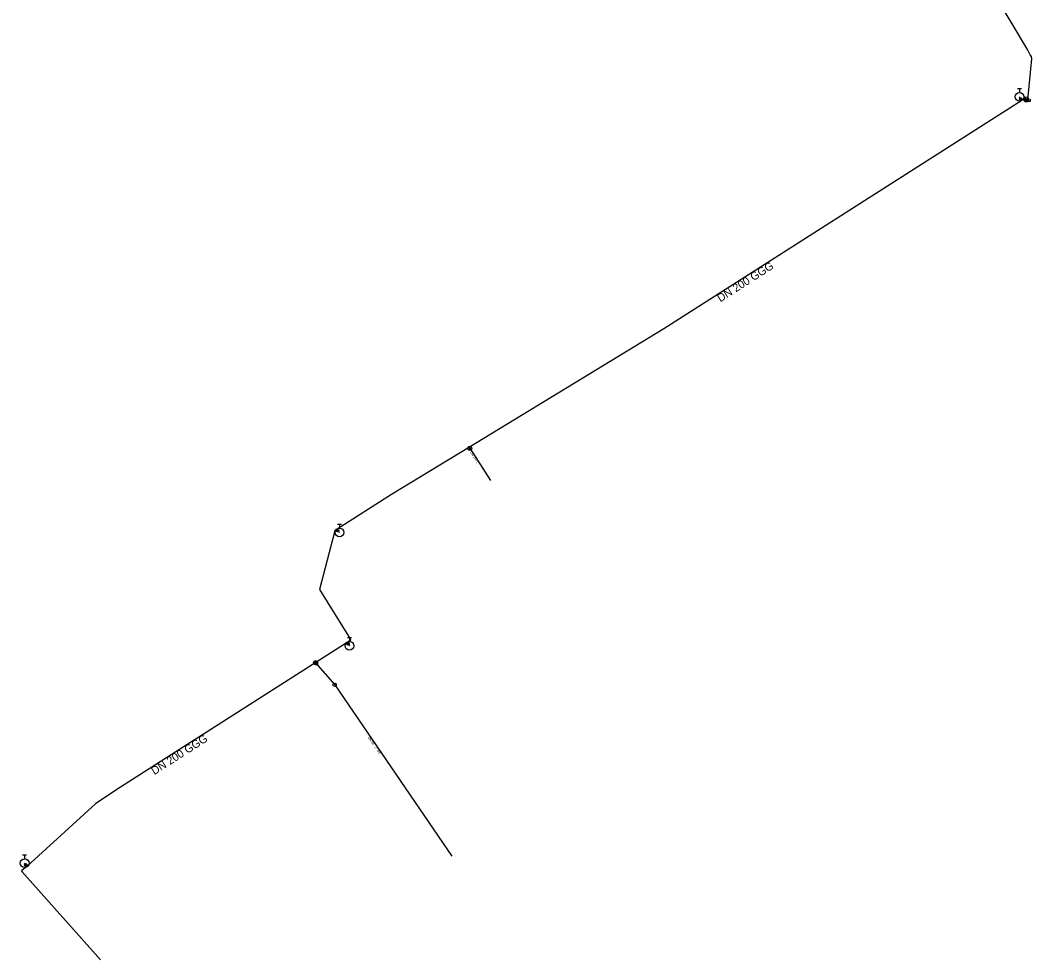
# Model space of a CAD drawing. Extents: x -451555 to -451079, y -1102113 to -1101586.
# Drawn here: x -451282.2 to -451079.4, y -1102113.4 to -1101925 of the extents above; entities that cross this region are included whole.
import ezdxf

# ---------------------------------------------------------------- set-up
doc = ezdxf.new("R2010")
doc.units = 0
for name, color, linetype in [('_hydrantova_odbocka_', 7, 'Continuous'), ('_pripojka_prevzato_z_dokumentace_', 7, 'Continuous'), ('_pripojka_priblizne_', 7, 'Continuous'), ('_voda_smvak_prevzato_z_dokumentace_', 7, 'Continuous'), ('Default', 7, 'Continuous'), ('MoLevel 27', 7, 'Continuous'), ('MoLevel 28', 7, 'Continuous'), ('MoLevel 30', 7, 'Continuous'), ('MoLevel 32', 7, 'Continuous'), ('MoLevel 42', 7, 'Continuous'), ('MoLevel 43', 7, 'Continuous'), ('MoLevel 46', 7, 'Continuous'), ('MoLevel 53', 7, 'Continuous')]:
    doc.layers.add(name, color=color, linetype=linetype)

# ---------------------------------------------------------------- blocks, each defined once
blk = doc.blocks.new('_uzaver_')
at = {"layer": 'Default'}
for p, q in [((-0.000035, -0.000035), (0.000035, 0.000035)), ((0.000035, -0.000035), (-0.000035, 0.000035))]:
    blk.add_line(p, q, dxfattribs=at)
for radius in [0.00005, 0.0000025]:
    blk.add_circle((0, 0), radius, dxfattribs=at)
blk = doc.blocks.new('_uzaver_pripojka_')
at = {"layer": 'Default'}
for p, q in [((-0.000035, -0.000035), (0.000035, 0.000035)), ((0.000035, -0.000035), (-0.000035, 0.000035))]:
    blk.add_line(p, q, dxfattribs=at)
for radius in [0.00005, 0.0000025]:
    blk.add_circle((0, 0), radius, dxfattribs=at)
blk = doc.blocks.new('_hydrant_voda_')
at = {"layer": 'Default'}
for p, q in [((-0.000023, 0.000095), (0.000023, 0.000095)), ((0, 0.000095), (0, 0.00005))]:
    blk.add_line(p, q, dxfattribs=at)
blk.add_circle((0, 0), 0.00005, dxfattribs=at)
blk = doc.blocks.new('_zaslepeni_')
at = {"layer": 'Default'}
blk.add_lwpolyline([(-0.00004, -0.00005), (0, -0.00005), (0, 0.00005), (-0.00004, 0.00005), (-0.00004, 0.00005)], dxfattribs=at)
blk = doc.blocks.new('_sachta_voda_')
at = {"layer": 'Default'}
blk.add_circle((0, 0), 0.000035, dxfattribs=at)
blk = doc.blocks.new('_poklop_voda_')
at = {"layer": 'Default'}
blk.add_circle((0, 0), 0.00002, dxfattribs=at)

msp = doc.modelspace()

# ---------------------------------------------------------------- linework, layer by layer
at = {"layer": '_hydrantova_odbocka_'}
for p, q in [((-451081.59, -1101940.76), (-451081.82, -1101940.32)), ((-451081.37, -1101941.05), (-451081.59, -1101940.76)), ((-451218.64, -1102027.02), (-451218.56, -1102027.33)), ((-451218.56, -1102027.33), (-451218.18, -1102027.69)), ((-451216.63, -1102049.77), (-451216.46, -1102050.04)), ((-451216.46, -1102050.04), (-451216.18, -1102050.42)), ((-451281.05, -1102094.37), (-451281.3, -1102094.02)), ((-451280.77, -1102094.65), (-451281.05, -1102094.37))]:
    msp.add_line(p, q, dxfattribs=at)
at = {"layer": '_pripojka_prevzato_z_dokumentace_'}
msp.add_line((-451222.97, -1102053.82), (-451219.13, -1102058.26), dxfattribs=at)
at = {"layer": '_pripojka_priblizne_'}
msp.add_line((-451219.13, -1102058.26), (-451195.67, -1102092.62), dxfattribs=at)
msp.add_lwpolyline([(-451192.13, -1102010.59), (-451192.05, -1102010.82), (-451187.91, -1102017.27)], dxfattribs=at)
at = {"layer": '_voda_smvak_prevzato_z_dokumentace_'}
for p, q in [((-451080.15, -1101940.92), (-451080.5, -1101940.86)), ((-451080.14, -1101941.19), (-451080.15, -1101940.92))]:
    msp.add_line(p, q, dxfattribs=at)
for points in [[(-451079.67, -1101931.88), (-451080.22, -1101930.82), (-451126.34, -1101853.56), (-451153.78, -1101812.57), (-451163.8, -1101796.36), (-451163.8, -1101796.36)], [(-451080.15, -1101940.92), (-451079.37, -1101932.69), (-451079.41, -1101932.26), (-451079.67, -1101931.88)], [(-451080.5, -1101940.86), (-451080.98, -1101940.79), (-451081.37, -1101941.05), (-451153.11, -1101986.86), (-451192.13, -1102010.59)], [(-451192.13, -1102010.59), (-451207.74, -1102020.11), (-451218.64, -1102027.02), (-451219.11, -1102027.35), (-451222.17, -1102039.13), (-451216.05, -1102049.02), (-451215.98, -1102049.23), (-451216.12, -1102049.41), (-451216.63, -1102049.77), (-451262.79, -1102079.25), (-451267.08, -1102082.11), (-451280.77, -1102094.65), (-451281.91, -1102095.54), (-451281.81, -1102095.74), (-451266.09, -1102113.4)]]:
    msp.add_lwpolyline(points, dxfattribs=at)

# ---------------------------------------------------------------- block references
at = {"layer": 'MoLevel 27', "xscale": 5000, "yscale": 5000}
for p in [(-451081.59, -1101940.76), (-451218.56, -1102027.33), (-451216.46, -1102050.04), (-451281.05, -1102094.37)]:
    msp.add_blockref('_uzaver_', p, dxfattribs=at)
at = {"layer": 'MoLevel 27', "xscale": 10000, "yscale": 10000, "rotation": 171.731050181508}
msp.add_blockref('_uzaver_', (-451080.5, -1101940.86), dxfattribs=at)
at = {"layer": 'MoLevel 28', "xscale": 17636.68430335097, "yscale": 17636.68430335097}
for p in [(-451081.82, -1101940.32), (-451218.18, -1102027.69), (-451216.18, -1102050.42), (-451281.3, -1102094.02)]:
    msp.add_blockref('_hydrant_voda_', p, dxfattribs=at)
at = {"layer": 'MoLevel 30', "xscale": 10000, "yscale": 10000}
msp.add_blockref('_sachta_voda_', (-451219.13, -1102058.26), dxfattribs=at)
at = {"layer": 'MoLevel 42', "xscale": 10000, "yscale": 10000}
msp.add_blockref('_poklop_voda_', (-451222.74, -1102054.1), dxfattribs=at)
at = {"layer": 'MoLevel 43', "xscale": 10000.000000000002, "yscale": 10000, "rotation": -87.87890277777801}
msp.add_blockref('_zaslepeni_', (-451080.14, -1101941.19), dxfattribs=at)
at = {"layer": 'MoLevel 53'}
for p, xscale, yscale, rotation in [((-451192.05, -1102010.82), 8000, 7999.999999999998, 23.690689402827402), ((-451222.97, -1102053.82), 7999.999999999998, 8000, -55.50000000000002)]:
    msp.add_blockref('_uzaver_pripojka_', p, dxfattribs=dict(at, xscale=xscale, yscale=yscale, rotation=rotation))

# ---------------------------------------------------------------- texts
at = {"layer": 'MoLevel 32'}
for s, rotation, p in [('DN 200 L', 302.6688, (-451192.06, -1102011.65)), ("DN 50 - 2'' IPE", 304.3288, (-451212.52, -1102068.88))]:
    msp.add_text(s, height=0.455, rotation=rotation, dxfattribs=at).set_placement(p)
at = {"layer": 'MoLevel 46'}
for rotation, p in [(32.5605, (-451141.82, -1101981.56)), (32.5643, (-451255.29, -1102076.37))]:
    msp.add_text('DN 200 GGG', height=1.605, rotation=rotation, dxfattribs=at).set_placement(p)

doc.saveas('drawing.dxf')
